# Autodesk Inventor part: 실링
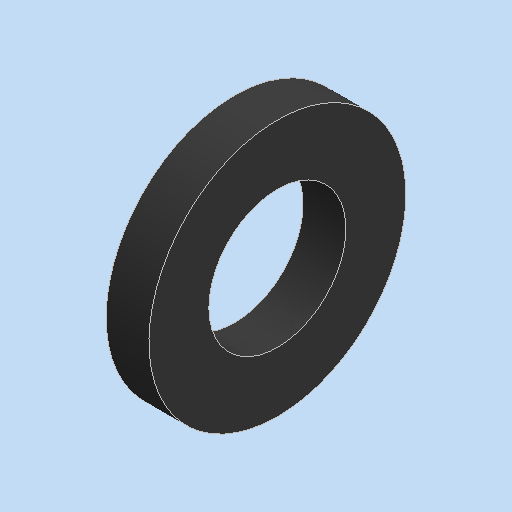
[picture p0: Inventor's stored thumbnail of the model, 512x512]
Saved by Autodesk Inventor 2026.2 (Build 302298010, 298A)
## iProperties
Created: 2026-03
Part Number: 실링
Material: 고무, 실리콘
Document SubType Name: Modeling
Designer: PC-2-03
Density: 1.25 g/cm^3
Appearance: 기본값
Author: jhkim
Sending System: Autodesk Inventor 2026
Preprocessor: ST-DEVELOPER v20.1
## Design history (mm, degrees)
feature "솔리드1"
node "솔리드2"
